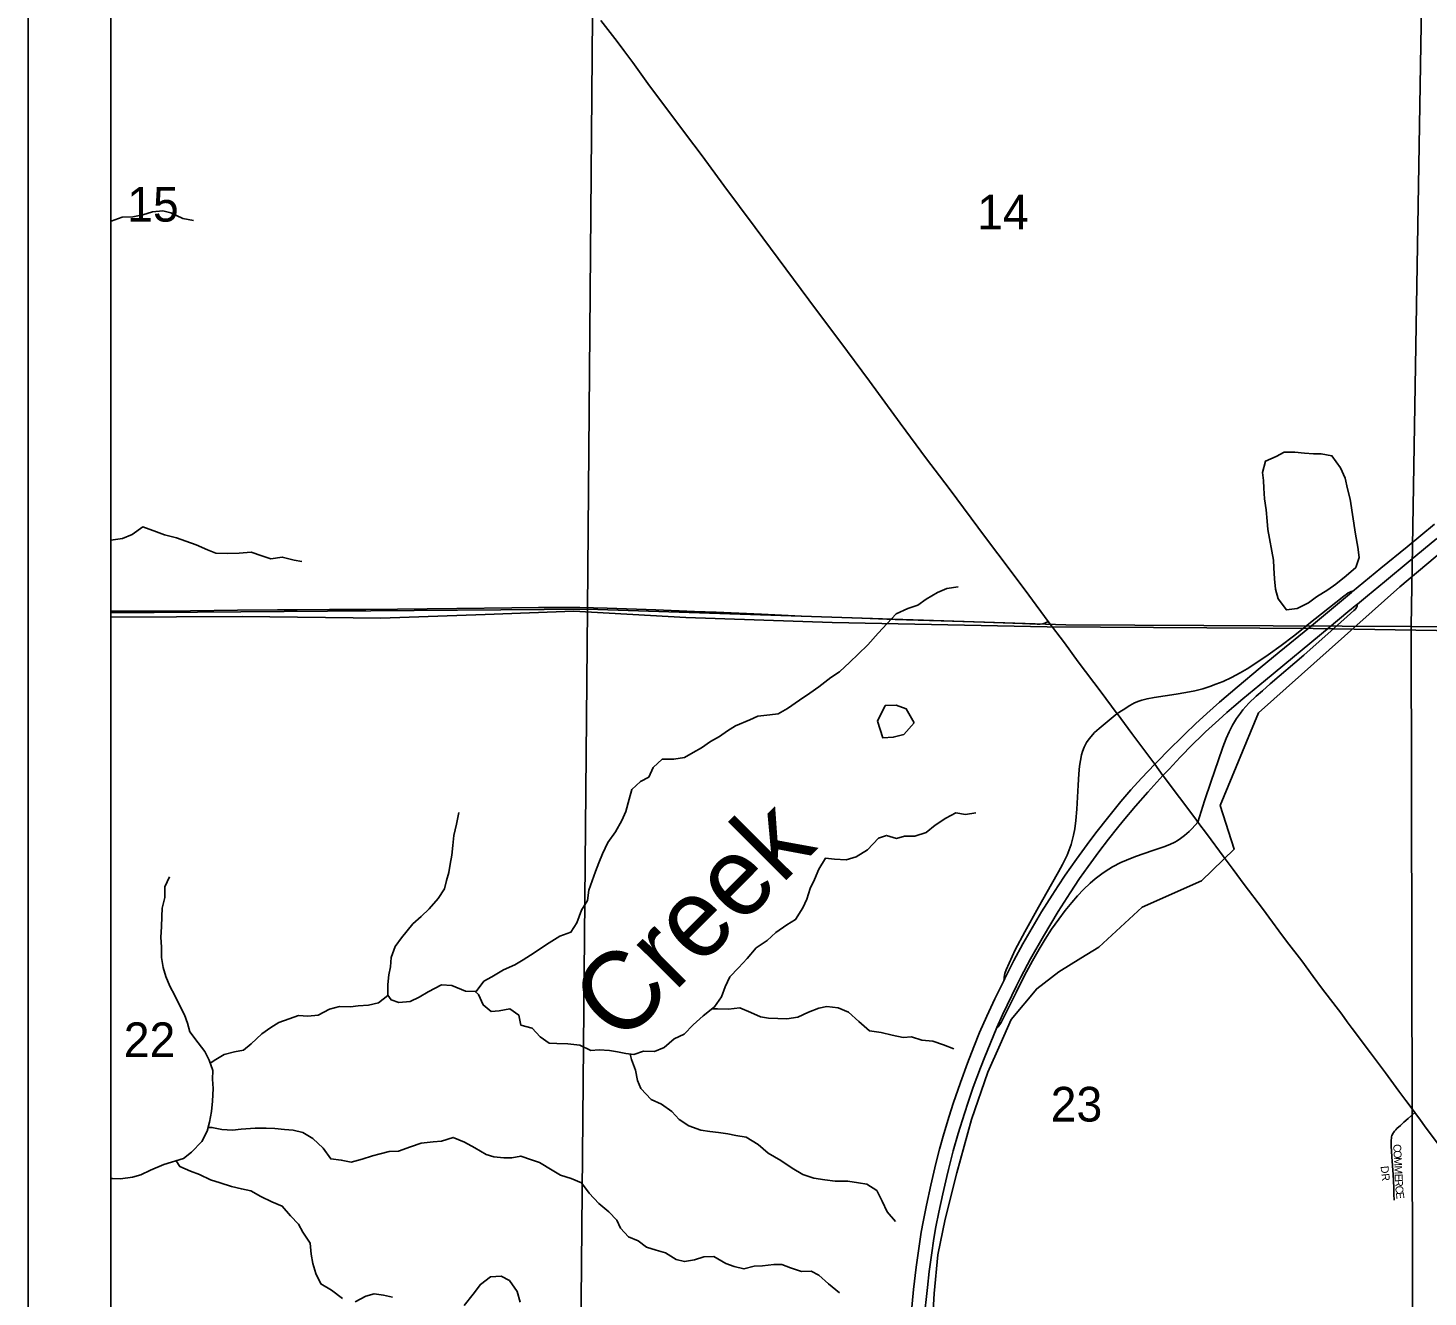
# Model space of a CAD drawing. Extents: x 0 to 1391, y -24 to 440.
# Drawn here: x 490 to 523.79, y 298.81 to 329.45 of the extents above; entities that cross this region are included whole.
import ezdxf

# ---------------------------------------------------------------- set-up
doc = ezdxf.new("R2010")
doc.units = 0
for name, color, linetype in [('GM_X_City_Street', 7, 'Continuous'), ('GM_X_City_Street_Text', 7, 'Continuous'), ('GM_X_Corporation', 7, 'Continuous'), ('GM_X_County_Road', 7, 'Continuous'), ('GM_X_Interchange_Ramps', 7, 'Continuous'), ('GM_X_Interstate_Route', 7, 'Continuous'), ('GM_X_Minor_Lake', 7, 'Continuous'), ('GM_X_Minor_River', 7, 'Continuous'), ('GM_X_Minor_River_Text', 7, 'Continuous'), ('GM_X_Section', 7, 'Continuous'), ('GM_X_Section_Text', 7, 'Continuous'), ('GM_X_State_Route', 7, 'Continuous'), ('GM_X_Township', 7, 'Continuous'), ('SH_Data', 7, 'Continuous')]:
    doc.layers.add(name, color=color, linetype=linetype)

msp = doc.modelspace()

# ---------------------------------------------------------------- linework, layer by layer
at = {"layer": 'GM_X_City_Street'}
msp.add_lwpolyline([(522.981, 301.147), (522.971, 301.292), (522.969, 301.452), (522.952, 301.773), (522.92, 302.195), (522.909, 302.459), (522.906, 302.556), (522.908, 302.6), (522.912, 302.644), (522.917, 302.676), (522.924, 302.709), (522.935, 302.737), (522.948, 302.762), (522.967, 302.79), (522.987, 302.814), (523.018, 302.845), (523.046, 302.878), (523.127, 302.956), (523.21, 303.032), (523.315, 303.123), (523.477, 303.264)], dxfattribs=at)
at = {"layer": 'GM_X_Corporation'}
msp.add_lwpolyline([(527.382, 319.542), (523.111, 315.958), (519.705, 312.916), (518.777, 310.679), (519.118, 309.622), (518.327, 308.86), (516.893, 308.224), (515.848, 307.261), (515.415, 306.993), (514.884, 306.664), (514.351, 306.253), (513.73, 305.511), (513.464, 304.911), (513.167, 304.243), (512.773, 303.099), (512.422, 301.81), (512.143, 300.687), (511.961, 299.826), (511.877, 298.895), (511.78, 297.253)], dxfattribs=at)
at = {"layer": 'GM_X_County_Road'}
msp.add_lwpolyline([(492, 315.371), (492.185, 315.373), (492.669, 315.372), (493.179, 315.372), (493.925, 315.382), (495.056, 315.394), (496.025, 315.399), (496.498, 315.402), (497.281, 315.407), (497.778, 315.407), (498.151, 315.408), (498.922, 315.422), (500.351, 315.433), (501.681, 315.447), (502.327, 315.458), (502.774, 315.461), (503.321, 315.457), (503.979, 315.44), (505.159, 315.4), (506.091, 315.366), (506.612, 315.343), (507.705, 315.295), (508.673, 315.253), (510.127, 315.202), (510.934, 315.173), (512.313, 315.125), (513.071, 315.102), (514.003, 315.07), (514.361, 315.06), (514.429, 315.06), (514.489, 315.066), (514.525, 315.075), (514.563, 315.09), (514.623, 315.124)], dxfattribs=at)
at = {"layer": 'GM_X_Interchange_Ramps'}
for points in [[(521.976, 315.846), (521.943, 315.842), (521.908, 315.832), (521.869, 315.811), (521.818, 315.774), (521.775, 315.74), (521.723, 315.699), (520.916, 315.063), (520.819, 314.985), (520.547, 314.768), (520.251, 314.543), (519.938, 314.318), (519.641, 314.114), (519.432, 313.981), (519.26, 313.88), (519.052, 313.77), (518.849, 313.675), (518.677, 313.604), (518.525, 313.549), (518.359, 313.497), (518.167, 313.448), (517.948, 313.403), (517.715, 313.365), (517.186, 313.289), (517.015, 313.256), (516.883, 313.222), (516.813, 313.198), (516.71, 313.154), (516.601, 313.095), (516.433, 312.988), (516.291, 312.901)], [(518.241, 310.277), (518.398, 310.795), (518.558, 311.265), (518.727, 311.758), (518.842, 312.086), (518.922, 312.295), (518.992, 312.454), (519.077, 312.62), (519.173, 312.779), (519.267, 312.911), (519.328, 312.989), (519.469, 313.146), (519.648, 313.318), (519.798, 313.449), (519.985, 313.612), (520.795, 314.308), (521.529, 314.963), (522.008, 315.389), (522.036, 315.414), (522.055, 315.437), (522.068, 315.457), (522.081, 315.488), (522.092, 315.543)], [(516.291, 312.901), (516.143, 312.778), (515.857, 312.539), (515.747, 312.438), (515.654, 312.338), (515.595, 312.259), (515.555, 312.196), (515.497, 312.086), (515.458, 311.982), (515.432, 311.899), (515.404, 311.765), (515.384, 311.63), (515.367, 311.445), (515.351, 311.172), (515.317, 310.589), (515.293, 310.316), (515.267, 310.119), (515.238, 309.961), (515.179, 309.733), (515.081, 309.478), (514.971, 309.255), (514.877, 309.08), (514.706, 308.777), (514.394, 308.226), (514.063, 307.629), (513.83, 307.19), (513.609, 306.707), (513.583, 306.625), (513.573, 306.579), (513.564, 306.531), (513.56, 306.502), (513.552, 306.444)], [(513.388, 305.317), (513.415, 305.333), (513.436, 305.358), (513.458, 305.389), (513.488, 305.437), (513.851, 306.163), (514.058, 306.573), (514.246, 306.924), (514.405, 307.206), (514.553, 307.451), (514.708, 307.691), (514.88, 307.935), (515.037, 308.143), (515.194, 308.336), (515.334, 308.495), (515.479, 308.649), (515.641, 308.804), (515.762, 308.91), (515.92, 309.032), (516.001, 309.088), (516.181, 309.199), (516.381, 309.3), (516.518, 309.359), (516.738, 309.445), (517.149, 309.589), (517.419, 309.683), (517.559, 309.736), (517.683, 309.793), (517.737, 309.824), (517.82, 309.878), (517.918, 309.954), (518.03, 310.052), (518.102, 310.121), (518.241, 310.277)]]:
    msp.add_lwpolyline(points, dxfattribs=at)
at = {"layer": 'GM_X_Interstate_Route'}
for points in [[(511.307, 298.299), (511.377, 298.991), (511.441, 299.534), (511.509, 300.038), (511.563, 300.381), (511.607, 300.626), (511.686, 301.028), (511.792, 301.513), (511.913, 302.033), (512.002, 302.382), (512.107, 302.752), (512.237, 303.18), (512.336, 303.487), (512.508, 303.993), (512.677, 304.46), (512.828, 304.854), (512.97, 305.198), (513.146, 305.596), (513.34, 306.012), (513.552, 306.444), (513.58, 306.503), (513.8, 306.934), (514.018, 307.339), (514.239, 307.727), (514.468, 308.111), (514.719, 308.511), (514.868, 308.74), (515.04, 308.998), (515.31, 309.385), (515.565, 309.737), (515.774, 310.015), (516.088, 310.416), (516.378, 310.772), (516.619, 311.055), (516.876, 311.342), (517.197, 311.673), (517.327, 311.804), (517.475, 311.955), (517.934, 312.409), (518.185, 312.649), (518.459, 312.902), (518.765, 313.174), (519.191, 313.536), (519.743, 313.999), (520.205, 314.377), (520.935, 314.978), (521.077, 315.096), (521.946, 315.82), (521.976, 315.846), (522.654, 316.406), (523.289, 316.926), (523.951, 317.471)], [(511.624, 298.25), (511.71, 299.041), (511.755, 299.424), (511.808, 299.819), (511.869, 300.225), (511.918, 300.507), (511.985, 300.861), (512.08, 301.299), (512.178, 301.723), (512.219, 301.893), (512.335, 302.338), (512.454, 302.757), (512.603, 303.245), (512.691, 303.517), (512.819, 303.881), (512.993, 304.348), (513.097, 304.614), (513.222, 304.926), (513.388, 305.317), (513.523, 305.622), (513.86, 306.322), (513.965, 306.536), (514.037, 306.671), (514.126, 306.838), (514.198, 306.973), (514.515, 307.521), (514.868, 308.121), (515.155, 308.572), (515.383, 308.913), (515.59, 309.208), (515.846, 309.56), (516.08, 309.866), (516.298, 310.138), (516.44, 310.311), (516.736, 310.663), (517.029, 311.001), (517.397, 311.403), (517.543, 311.559), (517.816, 311.847), (518.121, 312.158), (518.325, 312.358), (518.424, 312.453), (518.745, 312.747), (518.94, 312.92), (519.11, 313.066), (519.327, 313.252), (519.871, 313.706), (521.412, 314.974), (521.863, 315.353), (522.074, 315.528), (522.092, 315.543), (522.334, 315.74), (522.748, 316.078), (523.368, 316.595), (524.009, 317.127)]]:
    msp.add_lwpolyline(points, dxfattribs=at)
at = {"layer": 'GM_X_Minor_Lake'}
for p, q in [((522.041, 317.227), (521.915, 318.074)), ((519.926, 317.342), (520.065, 316.603))]:
    msp.add_line(p, q, dxfattribs=at)
for points in [[(521.915, 318.074), (521.851, 318.325), (521.794, 318.584), (521.684, 318.829), (521.477, 319.122), (521.219, 319.165), (521.029, 319.169), (520.816, 319.188), (520.581, 319.208), (520.323, 319.206), (520.131, 319.104), (519.87, 318.988), (519.797, 318.717), (519.824, 318.527), (519.829, 318.337), (519.847, 318.079), (519.888, 317.813), (519.914, 317.547), (519.926, 317.342)], [(520.065, 316.603), (520.07, 316.414), (520.088, 316.148), (520.114, 315.905), (520.179, 315.668), (520.379, 315.399), (520.639, 315.431), (520.914, 315.57), (521.107, 315.718), (521.376, 315.886), (521.568, 316.019), (521.823, 316.226), (522.054, 316.426), (522.134, 316.667), (522.1, 316.918), (522.041, 317.227)], [(511.392, 312.674), (511.202, 313.011), (510.953, 313.099), (510.694, 313.09), (510.508, 312.713)], [(510.508, 312.713), (510.635, 312.31), (510.886, 312.327), (511.138, 312.39), (511.392, 312.674)]]:
    msp.add_lwpolyline(points, dxfattribs=at)
at = {"layer": 'GM_X_Minor_River'}
for points in [[(492, 324.784), (492.006, 324.788), (492.273, 324.882), (492.532, 324.893), (492.769, 324.943), (493.005, 325.015), (493.257, 325.034), (493.446, 324.985), (493.734, 324.851), (493.992, 324.802)], [(492, 317.081), (492.003, 317.083), (492.285, 317.124), (492.515, 317.219), (492.775, 317.404), (493.101, 317.285), (493.298, 317.214), (493.586, 317.141), (493.813, 317.061), (494.056, 316.974), (494.336, 316.848), (494.532, 316.769), (494.806, 316.765), (495.095, 316.768), (495.385, 316.793), (495.642, 316.706), (495.862, 316.634), (496.136, 316.675), (496.424, 316.602), (496.614, 316.569)], [(498.69, 306.096), (498.766, 305.989), (498.955, 305.926), (499.222, 305.946), (499.444, 306.05), (499.658, 306.176), (499.979, 306.347), (500.23, 306.329), (500.564, 306.196), (500.815, 306.186), (501, 306.434), (501.199, 306.538), (501.482, 306.709), (501.75, 306.835), (501.949, 306.954), (502.217, 307.118), (502.515, 307.319), (502.837, 307.52), (503.104, 307.624), (503.251, 307.849), (503.36, 308.152), (503.507, 308.385), (503.539, 308.635), (503.695, 309.088), (503.781, 309.292), (503.866, 309.511), (503.998, 309.783), (504.183, 310.039), (504.338, 310.317), (504.431, 310.536), (504.51, 310.831), (504.58, 311.066), (504.787, 311.261), (504.986, 311.364), (505.087, 311.598), (505.31, 311.801), (505.591, 311.797), (505.851, 311.84), (506.057, 311.959), (506.256, 312.071), (506.478, 312.227), (506.692, 312.346), (506.884, 312.48), (507.075, 312.6), (507.427, 312.747), (507.618, 312.836), (507.908, 312.871), (508.106, 312.891), (508.335, 313.018), (508.626, 313.219), (508.871, 313.391), (509.086, 313.54), (509.377, 313.772), (509.591, 313.906), (509.837, 314.138), (510.037, 314.333), (510.275, 314.558), (510.521, 314.836), (510.736, 315.076), (510.959, 315.309), (511.241, 315.434), (511.478, 315.515), (511.677, 315.664), (511.953, 315.821), (512.182, 315.916), (512.457, 315.959)], [(494.399, 304.461), (494.535, 304.543), (494.734, 304.67), (494.986, 304.727), (495.199, 304.771), (495.391, 304.928), (495.644, 305.167), (495.859, 305.317), (496.058, 305.436), (496.302, 305.524), (496.531, 305.605), (496.752, 305.595), (497.004, 305.615), (497.279, 305.763), (497.523, 305.829), (497.782, 305.818), (497.972, 305.839), (498.216, 305.859), (498.46, 305.917), (498.69, 306.089), (498.685, 306.354), (498.71, 306.589), (498.749, 306.786), (498.767, 307.006), (498.86, 307.278), (499.014, 307.481), (499.291, 307.819), (499.491, 307.999), (499.683, 308.186), (499.898, 308.434), (500.052, 308.667), (500.1, 308.864), (500.162, 309.061), (500.187, 309.265), (500.227, 309.477), (500.259, 309.712), (500.276, 309.954), (500.34, 310.227), (500.403, 310.507)], [(500.794, 306.186), (500.876, 306.117), (500.988, 305.865), (501.184, 305.704), (501.375, 305.724), (501.634, 305.767), (501.846, 305.62), (501.897, 305.377), (502.171, 305.305), (502.367, 305.091), (502.579, 304.944), (502.769, 304.934), (503.035, 304.924), (503.317, 304.89), (503.59, 304.766), (503.788, 304.779), (504.039, 304.761), (504.229, 304.728), (504.434, 304.688), (504.624, 304.663), (504.861, 304.744), (505.12, 304.741), (505.357, 304.837), (505.595, 305.046), (505.839, 305.157), (506.054, 305.382), (506.3, 305.599), (506.568, 305.816), (506.738, 306.057), (506.831, 306.299), (506.94, 306.54), (507.147, 306.758), (507.362, 306.983), (507.578, 307.238), (507.846, 307.417), (508.053, 307.612), (508.314, 307.799), (508.528, 307.925), (508.705, 308.204), (508.798, 308.415), (508.877, 308.672), (508.985, 308.891), (509.094, 309.14), (509.248, 309.404), (509.469, 309.386), (509.751, 309.368), (509.995, 309.441), (510.263, 309.605), (510.532, 309.89), (510.723, 309.956), (510.966, 309.885), (511.157, 309.936), (511.408, 309.94), (511.683, 310.028), (511.897, 310.2), (512.158, 310.372), (512.395, 310.498), (512.63, 310.465), (512.882, 310.5)], [(492, 301.672), (492.036, 301.673), (492.234, 301.664), (492.524, 301.706), (492.722, 301.764), (492.959, 301.875), (493.28, 302.008), (493.753, 302.155), (493.945, 302.312), (494.199, 302.567), (494.323, 302.816), (494.385, 303.035), (494.426, 303.292), (494.451, 303.542), (494.468, 303.846), (494.455, 304.073), (494.464, 304.278), (494.375, 304.53), (494.27, 304.736), (494.105, 304.95), (493.909, 305.21), (493.85, 305.423), (493.775, 305.621), (493.648, 305.873), (493.543, 306.094), (493.423, 306.316), (493.326, 306.552), (493.26, 306.765), (493.224, 307.008), (493.226, 307.259), (493.205, 307.502), (493.222, 307.752), (493.232, 308.002), (493.241, 308.199), (493.305, 308.456), (493.307, 308.714), (493.415, 308.956)], [(506.511, 305.77), (506.644, 305.77), (506.91, 305.759), (507.185, 305.794), (507.45, 305.677), (507.678, 305.576), (507.876, 305.543), (508.104, 305.533), (508.317, 305.531), (508.584, 305.566), (508.844, 305.692), (509.088, 305.787), (509.286, 305.823), (509.56, 305.79), (509.803, 305.688), (510.052, 305.465), (510.317, 305.235), (510.591, 305.194), (510.864, 305.13), (511.123, 305.081), (511.328, 305.094), (511.579, 305.015), (511.838, 304.99), (512.103, 304.896), (512.346, 304.802)], [(504.532, 304.675), (504.57, 304.542), (504.667, 304.291), (504.71, 304.04), (504.793, 303.842), (505.042, 303.581), (505.292, 303.464), (505.542, 303.287), (505.715, 303.095), (505.95, 302.941), (506.238, 302.839), (506.459, 302.806), (506.672, 302.781), (506.892, 302.748), (507.09, 302.708), (507.333, 302.667), (507.629, 302.497), (507.87, 302.282), (508.173, 302.104), (508.446, 301.926), (508.704, 301.772), (508.969, 301.678), (509.235, 301.637), (509.486, 301.611), (509.791, 301.607), (510.05, 301.566), (510.247, 301.534), (510.49, 301.379), (510.617, 301.128), (510.736, 300.868), (510.94, 300.631)], [(494.348, 302.905), (494.438, 302.905), (494.681, 302.857), (494.939, 302.839), (495.145, 302.867), (495.48, 302.886), (495.747, 302.89), (495.96, 302.88), (496.188, 302.855), (496.401, 302.838), (496.637, 302.782), (496.879, 302.635), (497.128, 302.404), (497.309, 302.144), (497.56, 302.119), (497.803, 302.071), (498.063, 302.143), (498.315, 302.216), (498.505, 302.267), (498.719, 302.326), (498.94, 302.331), (499.23, 302.434), (499.49, 302.529), (499.779, 302.556), (499.985, 302.577), (500.26, 302.665), (500.533, 302.548), (500.783, 302.416), (501.056, 302.253), (501.246, 302.198), (501.489, 302.173), (501.679, 302.171), (501.893, 302.214), (502.151, 302.12), (502.348, 302.057), (502.651, 301.871), (502.856, 301.755), (503.114, 301.669), (503.364, 301.567), (503.545, 301.322), (503.779, 301.069), (504.021, 300.869), (504.217, 300.67), (504.299, 300.472), (504.495, 300.265), (504.731, 300.171), (504.927, 300.017), (505.163, 299.939), (505.39, 299.875), (505.648, 299.721), (505.845, 299.665), (506.089, 299.708), (506.311, 299.781), (506.555, 299.786), (506.843, 299.624), (507.047, 299.545), (507.283, 299.49), (507.527, 299.555), (507.733, 299.568), (508.007, 299.595), (508.198, 299.593), (508.41, 299.515), (508.668, 299.428), (508.904, 299.433), (509.094, 299.34), (509.32, 299.133), (509.585, 298.91)], [(493.579, 302.101), (493.669, 301.959), (493.926, 301.849), (494.138, 301.77), (494.403, 301.644), (494.638, 301.565), (494.911, 301.477), (495.153, 301.42), (495.381, 301.371), (495.623, 301.238), (495.887, 301.113), (496.137, 301.003), (496.339, 300.772), (496.527, 300.572), (496.631, 300.373), (496.811, 300.112), (496.838, 299.846), (496.873, 299.618), (496.946, 299.382), (497.072, 299.129), (497.329, 298.973), (497.593, 298.772)], [(500.527, 298.604), (500.743, 298.882), (500.921, 299.114), (501.166, 299.3), (501.425, 299.311), (501.622, 299.209), (501.808, 298.941), (501.881, 298.689)], [(497.896, 298.699), (498.156, 298.831), (498.355, 298.889), (498.583, 298.855), (498.795, 298.806)]]:
    msp.add_lwpolyline(points, dxfattribs=at)
at = {"layer": 'GM_X_Section'}
for p, q in [((492, 335.482), (492, 315.332)), ((492, 315.332), (492, 295.194))]:
    msp.add_line(p, q, dxfattribs=at)
for points in [[(492, 315.332), (503.508, 315.416), (503.672, 335.473), (492, 335.482)], [(492, 295.194), (503.319, 295.209), (503.508, 315.416), (492, 315.332)]]:
    msp.add_lwpolyline(points, dxfattribs=at)
for points in [[(523.728, 335.34), (523.385, 314.999), (515.053, 315.041), (503.508, 315.416), (503.672, 335.473)], [(543.597, 335.27), (543.606, 334.944), (543.593, 314.84), (523.385, 314.999), (523.728, 335.34)], [(503.508, 315.416), (515.053, 315.041), (523.385, 314.999), (523.431, 295.166), (503.319, 295.209)], [(543.593, 314.84), (543.458, 295.101), (523.431, 295.166), (523.385, 314.999)]]:
    msp.add_lwpolyline(points, close=True, dxfattribs=at)
at = {"layer": 'GM_X_State_Route'}
for points in [[(503.827, 329.634), (504.22, 329.122), (504.386, 328.905), (504.599, 328.614), (504.965, 328.111), (505.872, 326.897), (506.275, 326.36), (506.8, 325.65), (507.554, 324.632), (508.481, 323.385), (509.035, 322.636), (509.593, 321.889), (510.31, 320.92), (511.055, 319.91), (511.689, 319.05), (512.005, 318.635), (512.26, 318.298), (513.087, 317.178), (513.729, 316.324), (514.156, 315.758), (514.623, 315.124)], [(514.623, 315.124), (514.623, 315.124), (515.017, 314.609), (515.354, 314.148), (515.903, 313.412), (516.271, 312.927), (516.291, 312.901), (516.647, 312.418), (517.197, 311.673), (517.397, 311.403), (517.404, 311.394)], [(517.404, 311.394), (518.189, 310.345), (518.241, 310.277), (518.471, 309.972)], [(518.471, 309.972), (518.85, 309.455)], [(518.85, 309.455), (518.969, 309.294)], [(518.969, 309.294), (519.088, 309.132), (519.356, 308.774), (519.798, 308.189)], [(519.798, 308.189), (520.044, 307.862), (520.198, 307.651), (520.382, 307.401), (520.746, 306.928), (521.025, 306.548), (521.224, 306.277), (521.717, 305.638), (521.846, 305.455), (521.962, 305.294), (522.403, 304.708), (522.768, 304.221), (523.094, 303.782), (523.263, 303.552), (523.433, 303.322), (523.477, 303.264), (523.613, 303.085), (523.712, 302.943), (526.209, 299.597)]]:
    msp.add_lwpolyline(points, dxfattribs=at)
at = {"layer": 'GM_X_Township'}
for points in [[(492, 418), (492, 315.227), (495.169, 315.241), (498.514, 315.204), (501.039, 315.287), (503.177, 315.368), (505.882, 315.221), (509.415, 315.098), (514.601, 314.991), (521.022, 314.955), (531.927, 314.772), (538.532, 314.775), (540.688, 314.776), (542.014, 314.776), (543.525, 314.752), (551.45, 314.755), (558.142, 314.749), (563.346, 314.735), (563.436, 326.438), (563.505, 334.791), (563.576, 343.168), (563.677, 355.031), (563.749, 363.357), (563.752, 363.742)], [(531.927, 314.772), (521.022, 314.955), (514.601, 314.991), (509.415, 315.098), (505.882, 315.221), (503.177, 315.368), (501.039, 315.287), (498.514, 315.204), (495.169, 315.241), (492, 315.227)], [(492, 315.227), (492, 282), (569.034, 282)]]:
    msp.add_lwpolyline(points, dxfattribs=at)
at = {"layer": 'SH_Data'}
for p, q in [((490, 420), (490, 280)), ((492, 418), (492, 282)), ((492, 418), (492, 282))]:
    msp.add_line(p, q, dxfattribs=at)

# ---------------------------------------------------------------- texts
at = {"layer": 'GM_X_City_Street_Text'}
for s, height, rotation, p in [('C', 0.189, 272.7448, (522.954, 302.498)), ('O', 0.189, 272.7551, (522.962, 302.348)), ('M', 0.189, 272.7333, (522.97, 302.182)), ('DR', 0.1894, 276.0168, (522.65, 301.967)), ('M', 0.189, 272.7553, (522.979, 301.982)), ('E', 0.189, 272.7601, (522.989, 301.782)), ('R', 0.189, 272.9146, (522.995, 301.649)), ('C', 0.189, 275.3154, (523.003, 301.49)), ('E', 0.189, 276.6845, (523.018, 301.336))]:
    msp.add_text(s, height=height, rotation=rotation, dxfattribs=at).set_placement(p)
at = {"layer": 'GM_X_Minor_River_Text'}
msp.add_text('Creek', height=1.8944, rotation=45.0872, dxfattribs=at).set_placement((504.311, 304.867))
at = {"layer": 'GM_X_Section_Text'}
for s, p in [('15', (492.394, 324.775)), ('14', (512.911, 324.587)), ('22', (492.311, 304.604)), ('23', (514.686, 303.048))]:
    msp.add_text(s, height=0.8371, rotation=0, dxfattribs=at).set_placement(p)

doc.saveas('drawing.dxf')
